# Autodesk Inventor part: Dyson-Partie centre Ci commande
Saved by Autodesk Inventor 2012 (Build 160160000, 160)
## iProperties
Created: 2012-11
Part Number: Dyson-Partie centre Ci commande
Material: Default
Document SubType Name: Modeling
Designer: Administrateur
Density: 1 g/cm^3
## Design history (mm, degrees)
node "Dyson-Partie centre Ci commande1"
node "Dyson-Partie centre Ci commande"
node "Dyson-Partie centre Ci commande_1"
node "Dyson-Partie centre Ci commande_2"
node "Dyson-Partie centre Ci commande_3"
node "Dyson-Partie centre Ci commande_4"
node "Dyson-Partie centre Ci commande_5"
node "Dyson-Partie centre Ci commande_6"
node "Dyson-Partie centre Ci commande_7"
node "Dyson-Partie centre Ci commande_8"
node "Dyson-Partie centre Ci commande_9"
node "Dyson-Partie centre Ci commande_10"
node "Dyson-Partie centre Ci commande_11"
node "Dyson-Partie centre Ci commande_12"
node "Dyson-Partie centre Ci commande_13"
node "Dyson-Partie centre Ci commande_14"
node "Dyson-Partie centre Ci commande_15"
node "Dyson-Partie centre Ci commande_16"
node "Dyson-Partie centre Ci commande_17"
node "Dyson-Partie centre Ci commande_18"
node "Dyson-Partie centre Ci commande_19"
node "Dyson-Partie centre Ci commande_20"
node "Dyson-Partie centre Ci commande_21"
node "Dyson-Partie centre Ci commande_22"
node "Dyson-Partie centre Ci commande_23"
node "Dyson-Partie centre Ci commande_24"
node "Dyson-Partie centre Ci commande_25"
node "Dyson-Partie centre Ci commande_26"
node "Dyson-Partie centre Ci commande_27"
node "Base1"
node "Base2"
node "Base3"
node "Base4"
node "Base5"
node "Base6"
node "Base7"
node "Base8"
node "Base9"
node "Base10"
node "Base11"
node "Base12"
node "Base13"
node "Base14"
node "Base15"
node "Base16"
node "Base17"
node "Base18"
node "Base19"
node "Base20"
node "Base21"
node "Base22"
node "Base23"
node "Base24"
node "Base25"
node "Base26"
node "Base27"
node "Base28"
